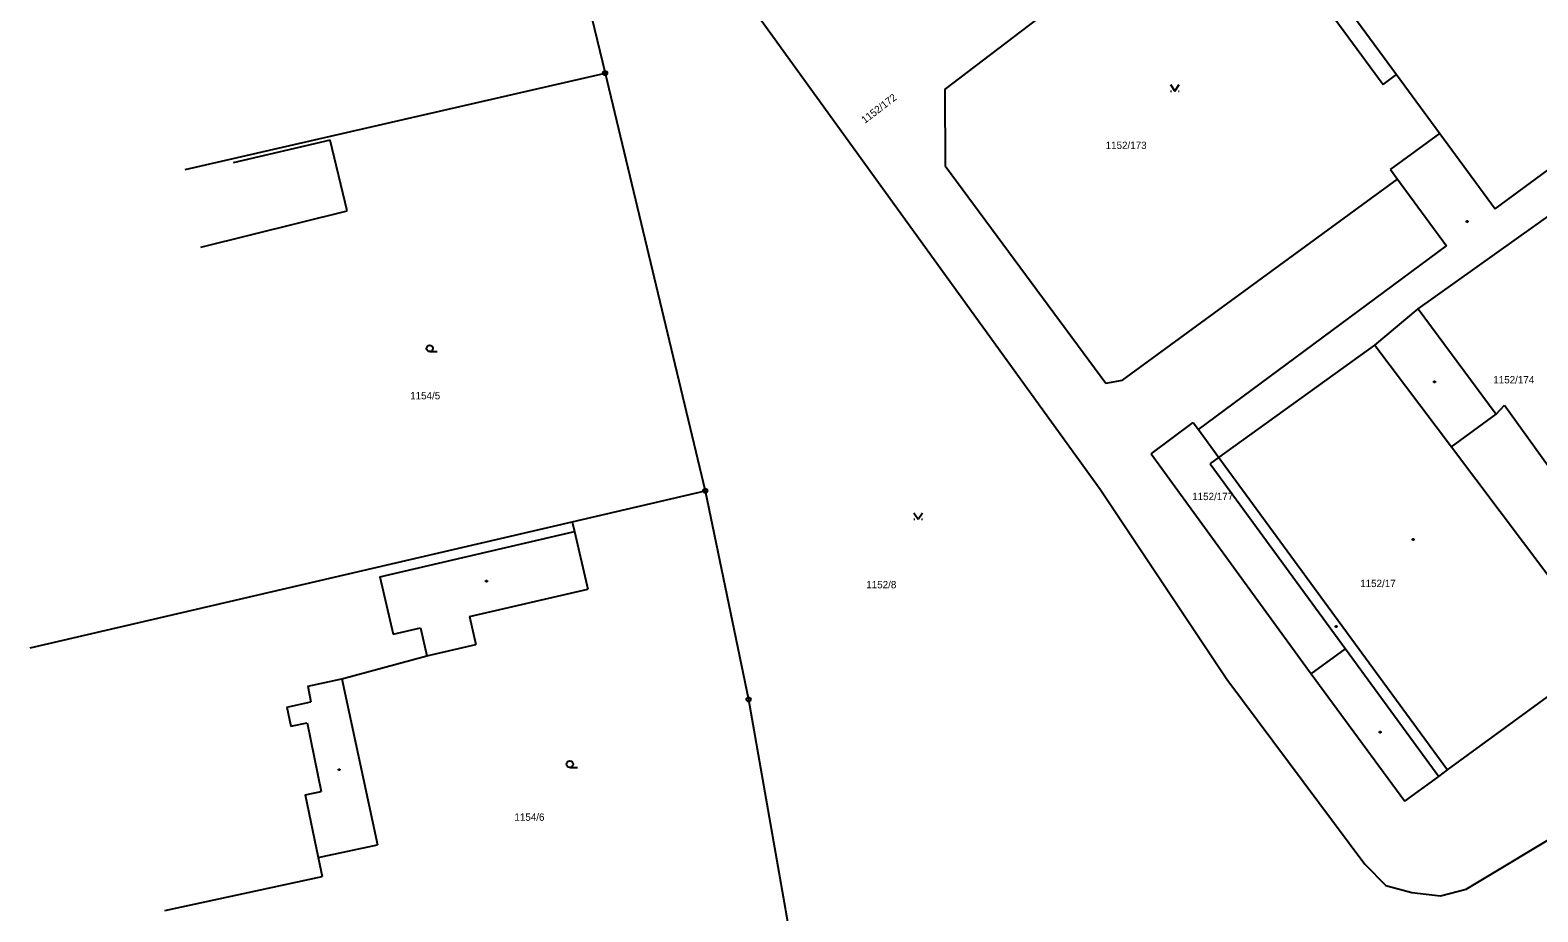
# Model space of a CAD drawing. Extents: x -609709 to -609357, y -1051535 to -1051131.
# Drawn here: x -609706.4 to -609619.2, y -1051439.6 to -1051388.6 of the extents above; entities that cross this region are included whole.
import ezdxf

# ---------------------------------------------------------------- set-up
doc = ezdxf.new("R2010")
doc.units = 0
doc.layers.add('Vrstva 10', color=7, linetype='Continuous')

msp = doc.modelspace()

# ---------------------------------------------------------------- linework, layer by layer
at = {"layer": 'Vrstva 10'}
for p, q in [((-609678.99, -1051366.71), (-609673.15, -1051391.07)), ((-609675.85, -1051371.78), (-609644.51, -1051415.13)), ((-609653.49, -1051392.02), (-609636.32, -1051378.94)), ((-609633.93, -1051383.85), (-609628.14, -1051391.73)), ((-609633.14, -1051383.27), (-609627.36, -1051391.16)), ((-609697.45, -1051396.64), (-609673.15, -1051391.07)), ((-609673.15, -1051391.07), (-609667.36, -1051415.23)), ((-609628.14, -1051391.73), (-609627.36, -1051391.16)), ((-609627.36, -1051391.16), (-609624.86, -1051394.57)), ((-609653.49, -1051392.02), (-609653.47, -1051396.44)), ((-609640.43, -1051391.735), (-609640.18, -1051392.11)), ((-609640.43, -1051392.11), (-609640.38, -1051392.11)), ((-609640.18, -1051392.11), (-609639.93, -1051391.735)), ((-609639.98, -1051392.11), (-609639.93, -1051392.11)), ((-609621.66, -1051398.92), (-609612.03, -1051391.85)), ((-609689.06, -1051394.95), (-609694.68, -1051396.27)), ((-609688.07, -1051399.04), (-609689.06, -1051394.95)), ((-609627.7, -1051396.65), (-609624.86, -1051394.57)), ((-609624.86, -1051394.57), (-609621.66, -1051398.92)), ((-609653.47, -1051396.44), (-609644.17, -1051409.01)), ((-609627.7, -1051396.65), (-609627.3, -1051397.2)), ((-609643.22, -1051408.84), (-609627.3, -1051397.2)), ((-609627.3, -1051397.2), (-609624.46, -1051401.06)), ((-609696.54, -1051401.13), (-609688.07, -1051399.04)), ((-609626.11, -1051404.7), (-609618.27, -1051399.14)), ((-609623.305, -1051399.625), (-609623.23, -1051399.625)), ((-609623.305, -1051399.7), (-609623.305, -1051399.625)), ((-609623.23, -1051399.7), (-609623.305, -1051399.7)), ((-609623.23, -1051399.625), (-609623.23, -1051399.7)), ((-609638.82, -1051411.68), (-609624.46, -1051401.06)), ((-609628.62, -1051406.8), (-609626.11, -1051404.7)), ((-609626.11, -1051404.7), (-609621.6, -1051410.79)), ((-609683.3, -1051407.18), (-609682.862, -1051407.18)), ((-609637.64, -1051413.3), (-609628.62, -1051406.8)), ((-609628.62, -1051406.8), (-609624.18, -1051412.69)), ((-609644.17, -1051409.01), (-609643.22, -1051408.84)), ((-609625.195, -1051408.885), (-609625.12, -1051408.885)), ((-609625.195, -1051408.96), (-609625.195, -1051408.885)), ((-609625.12, -1051408.96), (-609625.195, -1051408.96)), ((-609625.12, -1051408.885), (-609625.12, -1051408.96)), ((-609624.18, -1051412.69), (-609621.6, -1051410.79)), ((-609621.6, -1051410.79), (-609621.11, -1051410.27)), ((-609621.11, -1051410.27), (-609612.4, -1051422.42)), ((-609641.55, -1051413.09), (-609639.12, -1051411.28)), ((-609639.12, -1051411.28), (-609638.82, -1051411.68)), ((-609638.82, -1051411.68), (-609637.64, -1051413.3)), ((-609641.55, -1051413.09), (-609632.3, -1051425.81)), ((-609638.15, -1051413.68), (-609637.64, -1051413.3)), ((-609637.64, -1051413.3), (-609624.4, -1051431.37)), ((-609624.18, -1051412.69), (-609615.2, -1051424.63)), ((-609638.15, -1051413.68), (-609630.32, -1051424.37)), ((-609675.06, -1051417.02), (-609667.36, -1051415.23)), ((-609667.36, -1051415.23), (-609664.85, -1051427.3)), ((-609644.51, -1051415.13), (-609637.17, -1051426.12)), ((-609655.29, -1051416.505), (-609655.04, -1051416.88)), ((-609655.29, -1051416.88), (-609655.24, -1051416.88)), ((-609655.04, -1051416.88), (-609654.79, -1051416.505)), ((-609654.84, -1051416.88), (-609654.79, -1051416.88)), ((-609706.42, -1051424.32), (-609675.06, -1051417.02)), ((-609686.18, -1051420.2), (-609674.93, -1051417.59)), ((-609675.06, -1051417.02), (-609674.93, -1051417.59)), ((-609674.93, -1051417.59), (-609674.15, -1051420.92)), ((-609626.425, -1051418.005), (-609626.35, -1051418.005)), ((-609626.425, -1051418.08), (-609626.425, -1051418.005)), ((-609626.35, -1051418.08), (-609626.425, -1051418.08)), ((-609626.35, -1051418.005), (-609626.35, -1051418.08)), ((-609686.18, -1051420.2), (-609685.41, -1051423.52)), ((-609680.045, -1051420.415), (-609679.97, -1051420.415)), ((-609680.045, -1051420.49), (-609680.045, -1051420.415)), ((-609679.97, -1051420.49), (-609680.045, -1051420.49)), ((-609679.97, -1051420.415), (-609679.97, -1051420.49)), ((-609681, -1051422.5), (-609674.15, -1051420.92)), ((-609681, -1051422.5), (-609680.63, -1051424.12)), ((-609630.885, -1051423.045), (-609630.81, -1051423.045)), ((-609630.885, -1051423.12), (-609630.885, -1051423.045)), ((-609630.81, -1051423.12), (-609630.885, -1051423.12)), ((-609630.81, -1051423.045), (-609630.81, -1051423.12)), ((-609685.41, -1051423.52), (-609683.84, -1051423.16)), ((-609683.84, -1051423.16), (-609683.47, -1051424.77)), ((-609688.38, -1051426.1), (-609683.47, -1051424.77)), ((-609683.47, -1051424.77), (-609680.63, -1051424.12)), ((-609632.3, -1051425.81), (-609630.32, -1051424.37)), ((-609630.32, -1051424.37), (-609624.92, -1051431.75)), ((-609624.4, -1051431.37), (-609615.2, -1051424.63)), ((-609690.36, -1051426.53), (-609688.38, -1051426.1)), ((-609690.36, -1051426.53), (-609690.17, -1051427.44)), ((-609688.38, -1051426.1), (-609686.32, -1051435.7)), ((-609637.17, -1051426.12), (-609629.19, -1051436.82)), ((-609632.3, -1051425.81), (-609626.88, -1051433.19)), ((-609691.56, -1051427.74), (-609690.17, -1051427.44)), ((-609664.85, -1051427.3), (-609662.59, -1051440.14)), ((-609691.56, -1051427.74), (-609691.33, -1051428.85)), ((-609691.33, -1051428.85), (-609690.4, -1051428.65)), ((-609690.4, -1051428.65), (-609689.58, -1051432.62)), ((-609628.345, -1051429.155), (-609628.27, -1051429.155)), ((-609628.345, -1051429.23), (-609628.345, -1051429.155)), ((-609628.27, -1051429.23), (-609628.345, -1051429.23)), ((-609628.27, -1051429.155), (-609628.27, -1051429.23)), ((-609688.585, -1051431.325), (-609688.51, -1051431.325)), ((-609688.585, -1051431.4), (-609688.585, -1051431.325)), ((-609688.51, -1051431.4), (-609688.585, -1051431.4)), ((-609688.51, -1051431.325), (-609688.51, -1051431.4)), ((-609675.19, -1051431.23), (-609674.752, -1051431.23)), ((-609626.88, -1051433.19), (-609624.92, -1051431.75)), ((-609624.92, -1051431.75), (-609624.4, -1051431.37)), ((-609690.51, -1051432.81), (-609689.58, -1051432.62)), ((-609623.33, -1051438.28), (-609612.82, -1051431.94)), ((-609690.51, -1051432.81), (-609689.75, -1051436.44)), ((-609689.75, -1051436.44), (-609686.32, -1051435.7)), ((-609689.75, -1051436.44), (-609689.52, -1051437.54)), ((-609629.19, -1051436.82), (-609627.98, -1051438.07)), ((-609698.62, -1051439.5), (-609689.52, -1051437.54)), ((-609627.98, -1051438.07), (-609626.48, -1051438.46)), ((-609626.48, -1051438.46), (-609624.82, -1051438.65)), ((-609624.82, -1051438.65), (-609623.33, -1051438.28))]:
    msp.add_line(p, q, dxfattribs=at)
for centre, radius in [((-609673.15, -1051391.07), 0.125), ((-609673.15, -1051391.07), 0.0025), ((-609683.3, -1051406.992), 0.188), ((-609667.36, -1051415.23), 0.125), ((-609667.36, -1051415.23), 0.0025), ((-609664.85, -1051427.3), 0.125), ((-609664.85, -1051427.3), 0.0025), ((-609675.19, -1051431.042), 0.188)]:
    msp.add_circle(centre, radius, dxfattribs=at)

# ---------------------------------------------------------------- texts
msp.add_text('1152/172', height=0.425, rotation=37.54683, dxfattribs=at).set_placement((-609658.12, -1051394.01))
for s, p in [('1152/173', (-609644.19, -1051395.46)), ('1152/174', (-609621.76, -1051409.02)), ('1154/5', (-609684.431, -1051409.94)), ('1152/177', (-609639.18, -1051415.77)), ('1152/8', (-609658.04, -1051420.87)), ('1152/17', (-609629.46, -1051420.8)), ('1154/6', (-609678.4, -1051434.32))]:
    msp.add_text(s, height=0.425, dxfattribs=at).set_placement(p)

doc.saveas('drawing.dxf')
